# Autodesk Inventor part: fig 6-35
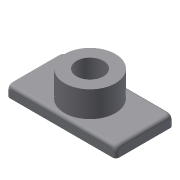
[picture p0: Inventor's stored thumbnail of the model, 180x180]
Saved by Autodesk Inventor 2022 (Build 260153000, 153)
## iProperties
Created: 2004-05
Part Number: fig 6-35
Document SubType Name: Modeling
Designer: CADCIM Technologies
Manufacturer: Standard
Standards Organization: Custom
Density: 1 g/cm^3
Material: Generic
Appearance: Default
Author: CADCIM Technologies
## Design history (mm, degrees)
sketch "Sketch1"
  geometry: L1 (-39.276, -18.692)-(33.721, -18.692); L2 (33.721, -18.692)-(33.721, 19.728); L3 (33.721, 19.728)-(-39.276, 19.728); L4 (-39.276, 19.728)-(-39.276, -18.692)
  constraints: 8 end point, 2 parallel, 1 horizontal, 1 perpendicular
extrude "Extrusion1" new body sketch "Sketch1" distance "d0" = 7.5; taper "d1" = 0 deg
sketch "Sketch2"
  geometry: C1 r 17 at (-2.778, 0.518)
  constraints: 1 centre point
  dimensions: "d16" = 34 diameter of C1
extrude "Extrusion2" join sketch "Sketch2" distance "d3" = 17.25; taper "d4" = 0 deg
hole "Hole1" diameter "d8" = 18; stored, may be unused: countersink angle "d12" = 90 deg, drill point angle "d14" = 118 deg; dims "d6" = 10, "d7" = 10, "d9" = 6, "d10" = 4, "d11" = 2, "d13" = 8
fillet "Fillet4" dims "d17" = 2
body "Solid1"
